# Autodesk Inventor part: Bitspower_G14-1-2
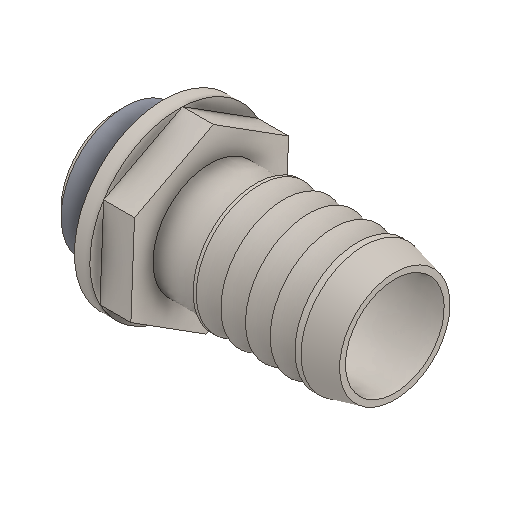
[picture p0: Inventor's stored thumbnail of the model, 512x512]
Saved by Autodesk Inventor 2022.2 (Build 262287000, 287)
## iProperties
Created: 2015-05
Part Number: Bitspower_G14-1-2
Material: Generico
Document SubType Name: Modeling
Designer: 18907419
Density: 1 g/cm^3
Appearance: Default
Author: 18907419
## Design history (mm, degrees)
feature "Solido1"
node "Solido2"
